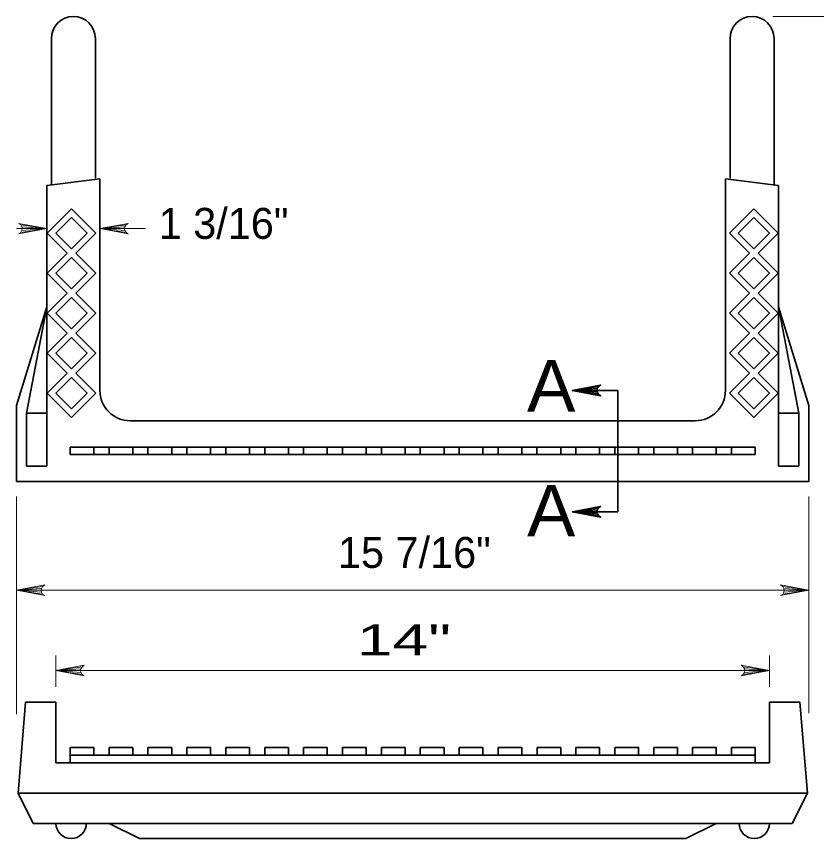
# Model space of a CAD drawing. Extents: x 15 to 140, y -57 to 117.
# Drawn here: x 21.42 to 47.78, y 82.72 to 109.82 of the extents above; entities that cross this region are included whole.
import ezdxf
from ezdxf.enums import TextEntityAlignment as Align

# ---------------------------------------------------------------- set-up
doc = ezdxf.new("R2010")
doc.units = 0
doc.header["$LTSCALE"] = 0.41
for name, color, linetype, lineweight in [('1', 7, 'Continuous', 35), ('10', 7, 'Continuous', 13), ('12', 7, 'Continuous', 53), ('13', 7, 'Continuous', 53), ('6', 7, 'Continuous', 13)]:
    doc.layers.add(name, color=color, linetype=linetype, lineweight=lineweight)

msp = doc.modelspace()

# ---------------------------------------------------------------- linework, layer by layer
at = {"layer": '1'}
for p, q in [((22.5747, 104.2695), (22.5747, 109.0953)), ((24.0247, 109.0953), (24.0247, 104.4945)), ((44.9273, 109.0953), (44.9273, 104.4945)), ((46.3773, 104.2695), (46.3773, 109.0953)), ((24.1747, 104.464), (22.4247, 104.2453)), ((24.1747, 97.4953), (24.1747, 104.464)), ((44.7773, 97.4953), (44.7773, 104.464)), ((44.7773, 104.464), (46.5273, 104.2453)), ((22.4247, 94.9953), (22.4247, 104.2453)), ((46.5273, 94.9953), (46.5273, 104.2453)), ((22.4247, 100.2453), (21.4247, 96.9953)), ((22.4247, 100.2453), (21.758, 96.7453)), ((46.5273, 100.2453), (47.5273, 96.9953)), ((46.5273, 100.2453), (47.194, 96.7453)), ((21.4247, 94.4953), (21.4247, 96.9953)), ((21.758, 94.9953), (21.758, 96.7453)), ((21.758, 96.7453), (22.4247, 96.7453)), ((47.194, 96.7453), (46.5273, 96.7453)), ((47.194, 94.9953), (47.194, 96.7453)), ((25.1747, 96.4953), (43.7773, 96.4953)), ((23.1947, 95.3788), (23.1947, 95.6288)), ((23.1947, 95.6288), (45.7573, 95.6288)), ((45.7573, 95.3788), (23.1947, 95.3788)), ((23.976, 95.6288), (23.976, 95.3788)), ((24.476, 95.3788), (24.476, 95.6288)), ((25.2573, 95.6288), (25.2573, 95.3788)), ((25.7573, 95.3788), (25.7573, 95.6288)), ((26.5386, 95.6288), (26.5386, 95.3788)), ((27.0386, 95.3788), (27.0386, 95.6288)), ((27.8199, 95.6288), (27.8199, 95.3788)), ((28.3199, 95.3788), (28.3199, 95.6288)), ((29.1012, 95.6288), (29.1012, 95.3788)), ((29.6012, 95.3788), (29.6012, 95.6288)), ((30.3825, 95.6288), (30.3825, 95.3788)), ((30.8825, 95.3788), (30.8825, 95.6288)), ((31.6638, 95.6288), (31.6638, 95.3788)), ((32.1638, 95.3788), (32.1638, 95.6288)), ((32.9451, 95.3788), (32.9451, 95.6288)), ((32.9451, 95.6288), (32.9451, 95.3788)), ((33.4451, 95.3788), (33.4451, 95.6288)), ((34.2264, 95.6288), (34.2264, 95.3788)), ((34.7256, 95.6288), (34.7256, 95.3788)), ((35.5069, 95.3788), (35.5069, 95.6288)), ((36.0069, 95.3788), (36.0069, 95.6288)), ((36.0069, 95.6288), (36.0069, 95.3788)), ((36.7882, 95.3788), (36.7882, 95.6288)), ((37.2882, 95.6288), (37.2882, 95.3788)), ((38.0695, 95.3788), (38.0695, 95.6288)), ((38.5695, 95.6288), (38.5695, 95.3788)), ((39.3508, 95.3788), (39.3508, 95.6288)), ((39.8508, 95.6288), (39.8508, 95.3788)), ((40.6321, 95.3788), (40.6321, 95.6288)), ((41.1321, 95.6288), (41.1321, 95.3788)), ((41.9134, 95.3788), (41.9134, 95.6288)), ((42.4134, 95.6288), (42.4134, 95.3788)), ((43.1947, 95.3788), (43.1947, 95.6288)), ((43.6947, 95.6288), (43.6947, 95.3788)), ((44.476, 95.3788), (44.476, 95.6288)), ((44.476, 95.3788), (44.476, 95.6288)), ((44.976, 95.6288), (44.976, 95.3788)), ((45.7573, 95.3788), (45.7573, 95.6288)), ((21.758, 94.9953), (22.4247, 94.9953)), ((47.194, 94.9953), (46.5273, 94.9953)), ((21.726, 87.2246), (21.476, 84.2246)), ((21.726, 87.2246), (22.726, 87.2246)), ((22.726, 85.2246), (22.726, 87.2246)), ((46.226, 85.2246), (46.226, 87.2246)), ((24.476, 85.4746), (24.476, 85.7246)), ((32.9451, 85.4746), (32.9451, 85.7246)), ((45.7573, 85.2246), (45.7573, 85.7246)), ((23.1947, 85.4746), (45.7573, 85.4746)), ((23.1947, 85.4746), (23.1947, 85.2246)), ((22.726, 85.2246), (46.226, 85.2246)), ((21.476, 84.2246), (47.476, 84.2246)), ((21.476, 84.2246), (21.976, 83.2246)), ((47.476, 84.2246), (46.976, 83.2246)), ((21.976, 83.2246), (46.976, 83.2246)), ((24.476, 83.2246), (25.476, 82.7246)), ((44.476, 83.2246), (43.476, 82.7246)), ((25.476, 82.7246), (43.476, 82.7246))]:
    msp.add_line(p, q, dxfattribs=at)
for points in [[(21.4247, 94.4953), (47.5273, 94.4953), (47.5273, 96.9953)], [(46.226, 87.2246), (47.226, 87.2246), (47.476, 84.2246)]]:
    msp.add_lwpolyline(points, dxfattribs=at)
for points in [[(23.1947, 85.7246), (23.976, 85.7246), (23.976, 85.4746), (23.1947, 85.4746)], [(24.476, 85.7246), (25.2573, 85.7246), (25.2573, 85.4746), (24.476, 85.4746)], [(25.7573, 85.7246), (26.5386, 85.7246), (26.5386, 85.4746), (25.7573, 85.4746)], [(27.0386, 85.7246), (27.8199, 85.7246), (27.8199, 85.4746), (27.0386, 85.4746)], [(28.3199, 85.7246), (29.1012, 85.7246), (29.1012, 85.4746), (28.3199, 85.4746)], [(29.6012, 85.7246), (30.3825, 85.7246), (30.3825, 85.4746), (29.6012, 85.4746)], [(30.8825, 85.7246), (31.6638, 85.7246), (31.6638, 85.4746), (30.8825, 85.4746)], [(32.1638, 85.7246), (32.9451, 85.7246), (32.9451, 85.4746), (32.1638, 85.4746)], [(33.4451, 85.7246), (34.2264, 85.7246), (34.2264, 85.4746), (33.4451, 85.4746)], [(34.7264, 85.7246), (35.5077, 85.7246), (35.5077, 85.4746), (34.7264, 85.4746)], [(36.0077, 85.7246), (36.789, 85.7246), (36.789, 85.4746), (36.0077, 85.4746)], [(37.289, 85.7246), (38.0703, 85.7246), (38.0703, 85.4746), (37.289, 85.4746)], [(38.5703, 85.7246), (39.3516, 85.7246), (39.3516, 85.4746), (38.5703, 85.4746)], [(39.8516, 85.7246), (40.6329, 85.7246), (40.6329, 85.4746), (39.8516, 85.4746)], [(41.1329, 85.7246), (41.9142, 85.7246), (41.9142, 85.4746), (41.1329, 85.4746)], [(42.4142, 85.7246), (43.1955, 85.7246), (43.1955, 85.4746), (42.4142, 85.4746)], [(43.6947, 85.7246), (44.476, 85.7246), (44.476, 85.4746), (43.6947, 85.4746)], [(44.976, 85.7246), (45.7573, 85.7246), (45.7573, 85.4746), (44.976, 85.4746)]]:
    msp.add_lwpolyline(points, close=True, dxfattribs=at)
for centre, radius, start, end in [((23.2997, 109.0953), 0.725, 0, 180), ((45.6523, 109.0953), 0.725, 0, 180), ((25.1747, 97.4953), 1, 180, 270), ((43.7773, 97.4953), 1, 270, 0), ((23.226, 83.2246), 0.5, 180, 0), ((45.726, 83.2246), 0.5, 180, 0)]:
    msp.add_arc(centre, radius, start, end, dxfattribs=at)
at = {"layer": '10'}
for p, q in [((46.3365, 109.8203), (58.1484, 109.8203)), ((21.4247, 102.8261), (22.4247, 102.8261)), ((24.1747, 102.8261), (25.6747, 102.8261)), ((21.4247, 93.9953), (21.4247, 86.8267)), ((47.5273, 93.9953), (47.5273, 86.858)), ((21.4247, 90.9077), (47.5273, 90.9077)), ((22.726, 87.7246), (22.726, 88.7591)), ((46.226, 87.7246), (46.226, 88.7591)), ((22.726, 88.2591), (46.226, 88.2591))]:
    msp.add_line(p, q, dxfattribs=at)
at = {"layer": '10', "lineweight": 35}
for p, q in [((39.7316, 97.4953), (41.2316, 97.4953)), ((41.2316, 97.4953), (41.2316, 93.4953)), ((39.7316, 93.4953), (41.2316, 93.4953))]:
    msp.add_line(p, q, dxfattribs=at)
at = {"layer": '10'}
for points in [[(22.4247, 102.8261), (21.4926, 102.6514), (21.5645, 102.7011), (21.6015, 102.7636), (21.6122, 102.8261), (21.6015, 102.8886), (21.5645, 102.9511), (21.4926, 103.0009), (22.4247, 102.8261), (21.5645, 102.9511), (21.6015, 102.8886), (22.4247, 102.8261), (21.6122, 102.8261), (21.6015, 102.7636), (22.4247, 102.8261), (21.5645, 102.7011)], [(24.1747, 102.8261), (25.1068, 103.0009), (25.035, 102.9511), (24.9979, 102.8886), (24.9872, 102.8261), (24.9979, 102.7636), (25.035, 102.7011), (25.1068, 102.6514), (24.1747, 102.8261), (25.035, 102.7011), (24.9979, 102.7636), (24.1747, 102.8261), (24.9872, 102.8261), (24.9979, 102.8886), (24.1747, 102.8261), (25.035, 102.9511)], [(21.4247, 90.9077), (22.3568, 91.0824), (22.285, 91.0327), (22.2479, 90.9702), (22.2372, 90.9077), (22.2479, 90.8452), (22.285, 90.7827), (22.3568, 90.7329), (21.4247, 90.9077), (22.285, 90.7827), (22.2479, 90.8452), (21.4247, 90.9077), (22.2372, 90.9077), (22.2479, 90.9702), (21.4247, 90.9077), (22.285, 91.0327)], [(47.5273, 90.9077), (46.5952, 90.7329), (46.667, 90.7827), (46.7041, 90.8452), (46.7148, 90.9077), (46.7041, 90.9702), (46.667, 91.0327), (46.5952, 91.0824), (47.5273, 90.9077), (46.667, 91.0327), (46.7041, 90.9702), (47.5273, 90.9077), (46.7148, 90.9077), (46.7041, 90.8452), (47.5273, 90.9077), (46.667, 90.7827)], [(22.726, 88.2591), (23.6581, 88.4339), (23.5862, 88.3841), (23.5492, 88.3216), (23.5385, 88.2591), (23.5492, 88.1966), (23.5862, 88.1341), (23.6581, 88.0843), (22.726, 88.2591), (23.5862, 88.1341), (23.5492, 88.1966), (22.726, 88.2591), (23.5385, 88.2591), (23.5492, 88.3216), (22.726, 88.2591), (23.5862, 88.3841)], [(46.226, 88.2591), (45.2939, 88.0843), (45.3657, 88.1341), (45.4028, 88.1966), (45.4135, 88.2591), (45.4028, 88.3216), (45.3657, 88.3841), (45.2939, 88.4339), (46.226, 88.2591), (45.3657, 88.3841), (45.4028, 88.3216), (46.226, 88.2591), (45.4135, 88.2591), (45.4028, 88.1966), (46.226, 88.2591), (45.3657, 88.1341)]]:
    msp.add_lwpolyline(points, dxfattribs=at)
at = {"layer": '10', "lineweight": 35}
for points in [[(39.7316, 97.4953), (40.6637, 97.67), (40.5919, 97.6203), (40.5549, 97.5578), (40.5441, 97.4953), (40.5549, 97.4328), (40.5919, 97.3703), (40.6637, 97.3205), (39.7316, 97.4953), (40.5919, 97.3703), (40.5549, 97.4328), (39.7316, 97.4953), (40.5441, 97.4953), (40.5549, 97.5578), (39.7316, 97.4953), (40.5919, 97.6203)], [(39.7316, 93.4953), (40.6637, 93.67), (40.5919, 93.6203), (40.5549, 93.5578), (40.5441, 93.4953), (40.5549, 93.4328), (40.5919, 93.3703), (40.6637, 93.3205), (39.7316, 93.4953), (40.5919, 93.3703), (40.5549, 93.4328), (39.7316, 93.4953), (40.5441, 93.4953), (40.5549, 93.5578), (39.7316, 93.4953), (40.5919, 93.6203)]]:
    msp.add_lwpolyline(points, dxfattribs=at)
at = {"layer": '6'}
for p, q in [((23.2392, 103.4758), (22.4392, 102.6758)), ((23.2392, 103.4758), (24.0392, 102.6758)), ((45.7128, 103.4758), (44.9128, 102.6758)), ((45.7128, 103.4758), (46.5128, 102.6758)), ((23.2392, 103.1929), (22.7221, 102.6758)), ((23.2392, 103.1929), (23.7564, 102.6758)), ((45.7128, 103.1929), (45.1956, 102.6758)), ((45.7128, 103.1929), (46.2299, 102.6758)), ((23.0978, 102.0172), (22.4392, 102.6758)), ((23.2392, 102.1586), (22.7221, 102.6758)), ((23.7564, 102.6758), (23.2392, 102.1586)), ((24.0392, 102.6758), (23.3807, 102.0172)), ((44.9128, 102.6758), (45.5713, 102.0172)), ((45.1956, 102.6758), (45.7128, 102.1586)), ((45.7128, 102.1586), (46.2299, 102.6758)), ((45.8542, 102.0172), (46.5128, 102.6758)), ((23.0978, 102.0172), (22.4392, 101.3586)), ((24.0392, 101.3586), (23.3807, 102.0172)), ((44.9128, 101.3586), (45.5713, 102.0172)), ((45.8542, 102.0172), (46.5128, 101.3586)), ((23.2392, 101.8758), (22.7221, 101.3586)), ((23.7564, 101.3586), (23.2392, 101.8758)), ((45.1956, 101.3586), (45.7128, 101.8758)), ((45.7128, 101.8758), (46.2299, 101.3586)), ((23.0978, 100.7), (22.4392, 101.3586)), ((23.2392, 100.8414), (22.7221, 101.3586)), ((23.7564, 101.3586), (23.2392, 100.8414)), ((24.0392, 101.3586), (23.3806, 100.7)), ((44.9128, 101.3586), (45.5714, 100.7)), ((45.1956, 101.3586), (45.7128, 100.8414)), ((45.7128, 100.8414), (46.2299, 101.3586)), ((45.8542, 100.7), (46.5128, 101.3586)), ((23.0978, 100.7), (22.4392, 100.0414)), ((23.2392, 100.5586), (22.7221, 100.0414)), ((23.7564, 100.0415), (23.2392, 100.5586)), ((24.0392, 100.0414), (23.3806, 100.7)), ((44.9128, 100.0414), (45.5714, 100.7)), ((45.1956, 100.0415), (45.7128, 100.5586)), ((45.7128, 100.5586), (46.2299, 100.0414)), ((45.8542, 100.7), (46.5128, 100.0414)), ((23.0978, 99.3829), (22.4392, 100.0414)), ((23.2392, 99.5243), (22.7221, 100.0414)), ((23.7564, 100.0415), (23.2392, 99.5243)), ((24.0392, 100.0414), (23.3806, 99.3829)), ((44.9128, 100.0414), (45.5714, 99.3829)), ((45.1956, 100.0415), (45.7128, 99.5243)), ((45.7128, 99.5243), (46.2299, 100.0414)), ((45.8542, 99.3829), (46.5128, 100.0414)), ((23.0978, 99.3829), (22.4392, 98.7243)), ((23.2392, 99.2414), (22.7221, 98.7243)), ((23.7564, 98.7243), (23.2392, 99.2414)), ((24.0392, 98.7243), (23.3806, 99.3829)), ((44.9128, 98.7243), (45.5714, 99.3829)), ((45.1956, 98.7243), (45.7128, 99.2414)), ((45.7128, 99.2414), (46.2299, 98.7243)), ((45.8542, 99.3829), (46.5128, 98.7243)), ((23.0978, 98.0657), (22.4392, 98.7243)), ((23.2392, 98.2071), (22.7221, 98.7243)), ((23.7564, 98.7243), (23.2392, 98.2071)), ((24.0392, 98.7243), (23.3806, 98.0657)), ((44.9128, 98.7243), (45.5714, 98.0657)), ((45.1956, 98.7243), (45.7128, 98.2071)), ((45.7128, 98.2071), (46.2299, 98.7243)), ((45.8542, 98.0657), (46.5128, 98.7243)), ((23.0978, 98.0657), (22.4392, 97.4071)), ((23.2392, 97.9243), (22.722, 97.4071)), ((23.7564, 97.4071), (23.2392, 97.9243)), ((24.0392, 97.4071), (23.3806, 98.0657)), ((44.9128, 97.4071), (45.5714, 98.0657)), ((45.1956, 97.4071), (45.7128, 97.9243)), ((45.7128, 97.9243), (46.23, 97.4071)), ((45.8542, 98.0657), (46.5128, 97.4071)), ((23.2392, 96.6071), (22.4392, 97.4071)), ((24.0392, 97.4071), (23.2392, 96.6071)), ((44.9128, 97.4071), (45.7128, 96.6071)), ((45.7128, 96.6071), (46.5128, 97.4071))]:
    msp.add_line(p, q, dxfattribs=at)
for points in [[(23.7564, 97.4071), (23.2392, 96.89), (22.722, 97.4071)], [(45.1956, 97.4071), (45.7128, 96.89), (46.23, 97.4071)]]:
    msp.add_lwpolyline(points, dxfattribs=at)

# ---------------------------------------------------------------- texts
at = {"layer": '12', "width": 1.05}
for p in [(39.0375, 96.7997), (39.0375, 92.6819)]:
    msp.add_text('A', height=1.7, dxfattribs=at).set_placement(p, align=Align.CENTER)
at = {"layer": '13'}
for s, p in [('1 3/16"', (28.2479, 102.4895)), ('15 7/16"', (34.5317, 91.645))]:
    msp.add_text(s, height=1.02, dxfattribs=at).set_placement(p, align=Align.CENTER)
at = {"layer": '13', "width": 1.55}
msp.add_text('14"', height=1.02, dxfattribs=at).set_placement((34.1871, 88.7614), align=Align.CENTER)

doc.saveas('drawing.dxf')
